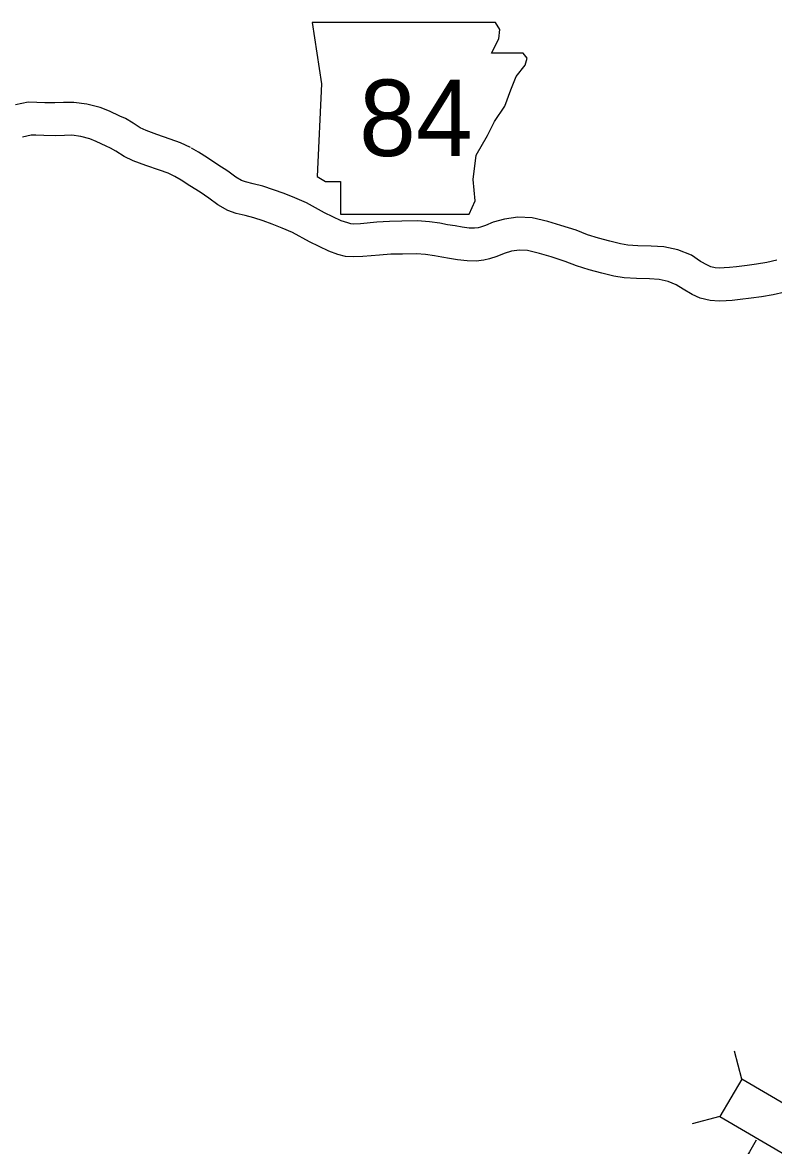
# Model space of a CAD drawing. Extents: x 1373862 to 1377080, y 1164775 to 1170415.
# Drawn here: x 1374409.6 to 1374478.2, y 1170151.1 to 1170253.6 of the extents above; entities that cross this region are included whole.
import ezdxf

# ---------------------------------------------------------------- set-up
doc = ezdxf.new("R2010")
doc.units = 0
doc.layers.add('Default', color=7, linetype='Continuous')

msp = doc.modelspace()

# ---------------------------------------------------------------- linework, layer by layer
at = {"layer": 'Default'}
for p, q in [((1374475.33, 1170157.16), (1374474.66, 1170159.71)), ((1374473.33, 1170153.74), (1374470.78, 1170153.07))]:
    msp.add_line(p, q, dxfattribs=at)
for points in [[(1374436.1, 1170253.57), (1374436.94, 1170247.98), (1374436.56, 1170239.52), (1374437.31, 1170239.05), (1374438.7, 1170239.05), (1374438.7, 1170236.07), (1374450.43, 1170236.07), (1374450.99, 1170237.28), (1374450.8, 1170239.24), (1374451.08, 1170241.47), (1374452.1, 1170243.24), (1374452.76, 1170244.54), (1374453.69, 1170245.94), (1374454.24, 1170247.43), (1374454.71, 1170248.63), (1374455.55, 1170249.66), (1374455.73, 1170250.31), (1374455.36, 1170250.78), (1374452.48, 1170250.78), (1374453.13, 1170252.08), (1374453.22, 1170252.92), (1374452.83, 1170253.56)], [(1374485.59, 1170151.17), (1374475.33, 1170157.16), (1374473.33, 1170153.74), (1374483.59, 1170147.75)]]:
    msp.add_lwpolyline(points, close=True, dxfattribs=at)
for points in [[(1374424.98, 1170242.16), (1374424.07, 1170242.59), (1374423.14, 1170242.91), (1374421.91, 1170243.35), (1374420.93, 1170243.7), (1374420.41, 1170243.96), (1374419.75, 1170244.38), (1374419.06, 1170244.79), (1374418.53, 1170245.02), (1374417.6, 1170245.46), (1374416.75, 1170245.81), (1374415.54, 1170246.12), (1374414.33, 1170246.27), (1374413.4, 1170246.26), (1374412.61, 1170246.22), (1374411.69, 1170246.24), (1374410.96, 1170246.27), (1374410.16, 1170246.29), (1374409.02, 1170246.04)], [(1374423.68, 1170239.45), (1374422.94, 1170239.81), (1374422.15, 1170240.08), (1374420.9, 1170240.52), (1374419.75, 1170240.93), (1374418.93, 1170241.34), (1374418.17, 1170241.83), (1374417.69, 1170242.11), (1374417.28, 1170242.29), (1374416.39, 1170242.72), (1374415.8, 1170242.96), (1374414.98, 1170243.17), (1374414.16, 1170243.27), (1374413.48, 1170243.26), (1374412.64, 1170243.22), (1374411.61, 1170243.25), (1374410.88, 1170243.27), (1374410.44, 1170243.28), (1374409.66, 1170243.11)], [(1374478.51, 1170231.87), (1374477.61, 1170231.66), (1374476.67, 1170231.51), (1374475.8, 1170231.39), (1374474.84, 1170231.28), (1374474.2, 1170231.2), (1374473.71, 1170231.17), (1374473.27, 1170231.14), (1374472.9, 1170231.17), (1374472.5, 1170231.27), (1374472.18, 1170231.41), (1374471.56, 1170231.77), (1374470.73, 1170232.33), (1374469.48, 1170232.81), (1374468.21, 1170233.09), (1374467.04, 1170233.16), (1374465.84, 1170233.2), (1374464.92, 1170233.25), (1374464.24, 1170233.36), (1374463.29, 1170233.6), (1374462.24, 1170233.88), (1374461.25, 1170234.2), (1374460.2, 1170234.6), (1374458.8, 1170235.05), (1374457.62, 1170235.4), (1374456.17, 1170235.75), (1374454.89, 1170235.8), (1374453.67, 1170235.63), (1374452.63, 1170235.33), (1374451.91, 1170235.03), (1374451.47, 1170234.89), (1374451.27, 1170234.84), (1374450.91, 1170234.81), (1374450.42, 1170234.81), (1374449.8, 1170234.88), (1374449.14, 1170235), (1374448.44, 1170235.11), (1374447.75, 1170235.24), (1374446.8, 1170235.37), (1374445.73, 1170235.46), (1374444.3, 1170235.43), (1374443.15, 1170235.42), (1374441.99, 1170235.33), (1374440.51, 1170235.19), (1374439.9, 1170235.17), (1374439.64, 1170235.19), (1374439.35, 1170235.27), (1374438.76, 1170235.48), (1374437.23, 1170236.21), (1374435.59, 1170237.1), (1374434.51, 1170237.56), (1374433.53, 1170237.96), (1374432.58, 1170238.31), (1374431.59, 1170238.62), (1374430.72, 1170238.85), (1374430.02, 1170239.03), (1374429.64, 1170239.16), (1374429.13, 1170239.44), (1374428.4, 1170240), (1374427.49, 1170240.59), (1374426.54, 1170241.2), (1374425.72, 1170241.73), (1374425.09, 1170242.1)], [(1374479.26, 1170228.97), (1374478.19, 1170228.72), (1374477.11, 1170228.54), (1374476.17, 1170228.42), (1374475.19, 1170228.3), (1374474.46, 1170228.21), (1374473.91, 1170228.18), (1374473.25, 1170228.14), (1374472.44, 1170228.2), (1374471.53, 1170228.41), (1374470.8, 1170228.74), (1374469.97, 1170229.23), (1374469.34, 1170229.64), (1374468.61, 1170229.93), (1374467.79, 1170230.11), (1374466.91, 1170230.16), (1374465.7, 1170230.2), (1374464.59, 1170230.27), (1374463.64, 1170230.42), (1374462.55, 1170230.69), (1374461.39, 1170231), (1374460.24, 1170231.37), (1374459.21, 1170231.77), (1374457.92, 1170232.18), (1374456.84, 1170232.5), (1374455.75, 1170232.77), (1374455.04, 1170232.8), (1374454.3, 1170232.69), (1374453.62, 1170232.5), (1374452.95, 1170232.22), (1374452.28, 1170232), (1374451.76, 1170231.88), (1374451.06, 1170231.8), (1374450.24, 1170231.81), (1374449.37, 1170231.91), (1374448.64, 1170232.04), (1374447.93, 1170232.15), (1374447.27, 1170232.27), (1374446.46, 1170232.39), (1374445.63, 1170232.46), (1374444.35, 1170232.43), (1374443.28, 1170232.42), (1374442.24, 1170232.34), (1374440.71, 1170232.2), (1374439.84, 1170232.17), (1374439.13, 1170232.22), (1374438.44, 1170232.41), (1374437.61, 1170232.71), (1374435.87, 1170233.54), (1374434.29, 1170234.4), (1374433.35, 1170234.79), (1374432.45, 1170235.17), (1374431.62, 1170235.47), (1374430.76, 1170235.74), (1374429.98, 1170235.94), (1374429.16, 1170236.15), (1374428.4, 1170236.41), (1374427.48, 1170236.93), (1374426.66, 1170237.55), (1374425.86, 1170238.08), (1374424.93, 1170238.67), (1374424.15, 1170239.17), (1374423.57, 1170239.52)], [(1374476.64, 1170151.58), (1374476.02, 1170150.51), (1374474.65, 1170148.28), (1374473.5, 1170146.56), (1374471.79, 1170144.15), (1374469.88, 1170141.75), (1374453.76, 1170121.89), (1374439.24, 1170103.99), (1374422.93, 1170084.13)]]:
    msp.add_lwpolyline(points, dxfattribs=at)

# ---------------------------------------------------------------- texts
msp.add_text('84', height=6.97, dxfattribs=at).set_placement((1374440.38, 1170241.38))

doc.saveas('drawing.dxf')
